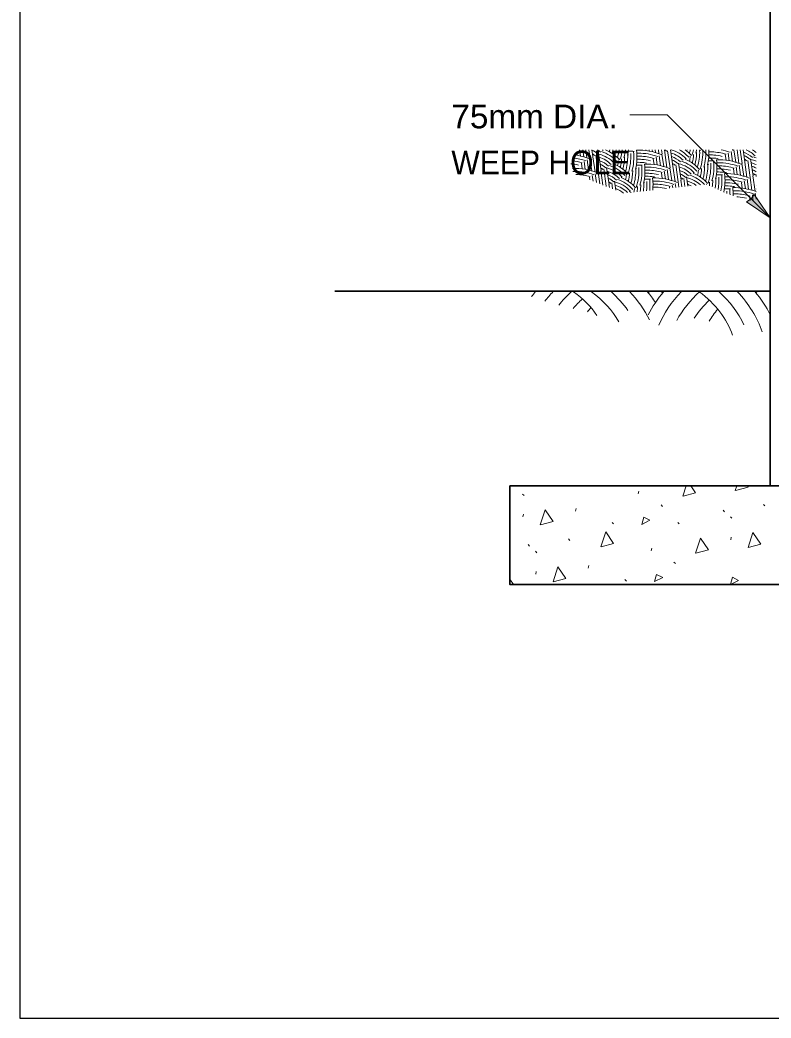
# Model space of a CAD drawing. Extents: x 17672 to 18472, y -9785 to -9267.
# Drawn here: x 17671.8 to 17783.6, y -9784.8 to -9636.2 of the extents above; entities that cross this region are included whole.
import ezdxf

# ---------------------------------------------------------------- set-up
doc = ezdxf.new("R2010")
doc.units = 0
doc.header["$LTSCALE"] = 1.4
for name, color, linetype, lineweight in [('1', 7, 'Continuous', 13), ('15', 7, 'Continuous', 13), ('16', 7, 'Continuous', 13), ('30', 7, 'Continuous', 25), ('59', 7, 'Continuous', 13)]:
    doc.layers.add(name, color=color, linetype=linetype, lineweight=lineweight)
doc.layers.add('19', color=7, linetype='Continuous')

msp = doc.modelspace()

# ---------------------------------------------------------------- hatches: boundary and pattern name
at = {"layer": '16'}
msp.add_hatch(color=256, dxfattribs=at).paths.add_polyline_path([(17783.439, -9665.599), (17781.072, -9662.116), (17780.648, -9662.802), (17779.937, -9663.248)])

# ---------------------------------------------------------------- linework, layer by layer
at = {"layer": '1', "lineweight": 35}
msp.add_line((17783.439, -9676.547), (17718.64, -9676.547), dxfattribs=at)
at = {"layer": '1', "lineweight": 25}
msp.add_line((17783.488, -9680.039), (17783.463, -9679.799), dxfattribs=at)
at = {"layer": '1'}
for p, q in [((17763.824, -9706.683), (17763.927, -9706.285)), ((17770.451, -9707.06), (17770.947, -9705.526)), ((17778.265, -9706.202), (17778.483, -9705.526)), ((17746.608, -9706.736), (17746.821, -9706.952)), ((17754.471, -9709.278), (17754.562, -9708.898)), ((17767.243, -9708.366), (17767.439, -9708.585)), ((17776.464, -9709.138), (17776.677, -9709.369)), ((17782.469, -9708.3), (17782.68, -9708.516)), ((17746.657, -9710.136), (17746.745, -9709.741)), ((17777.54, -9710.131), (17777.751, -9710.347)), ((17759.942, -9710.962), (17760.152, -9711.178)), ((17769.721, -9710.974), (17769.932, -9711.19)), ((17753.434, -9713.42), (17753.645, -9713.636)), ((17777.586, -9713.531), (17777.675, -9713.136)), ((17747.429, -9714.259), (17747.645, -9714.489)), ((17748.505, -9715.251), (17748.716, -9715.467)), ((17765.733, -9715.195), (17765.822, -9714.8)), ((17748.552, -9718.651), (17748.64, -9718.256)), ((17756.38, -9717.79), (17756.469, -9717.396)), ((17769.14, -9716.881), (17769.349, -9717.08)), ((17761.836, -9719.477), (17762.047, -9719.692))]:
    msp.add_line(p, q, dxfattribs=at)
at = {"layer": '1', "lineweight": 35}
for points in [[(17783.439, -9705.506), (17783.439, -9573.439), (17794.636, -9573.056), (17807.886, -9705.526), (17783.439, -9705.526)], [(17783.439, -9705.526), (17744.709, -9705.526), (17744.709, -9720.224), (17850.016, -9720.224), (17850.016, -9705.526), (17807.886, -9705.526)]]:
    msp.add_lwpolyline(points, close=True, dxfattribs=at)
at = {"layer": '1'}
for points in [[(17771.655, -9705.526), (17772.349, -9706.553), (17770.498, -9707.05)], [(17780.057, -9705.526), (17780.182, -9705.707), (17778.312, -9706.195)], [(17749.231, -9711.322), (17749.956, -9709.08), (17751.147, -9710.827), (17749.277, -9711.312)], [(17758.25, -9714.621), (17758.976, -9712.379), (17760.15, -9714.112), (17758.297, -9714.614)], [(17772.344, -9715.558), (17773.069, -9713.317), (17774.26, -9715.063), (17772.39, -9715.55)], [(17780.177, -9714.714), (17780.9, -9712.472), (17782.074, -9714.207), (17780.206, -9714.71)], [(17751.143, -9719.832), (17751.866, -9717.592), (17753.04, -9719.325), (17751.172, -9719.827)], [(17744.709, -9719.425), (17745.226, -9720.183), (17745.066, -9720.224)], [(17777.537, -9720.224), (17777.831, -9719.134), (17778.748, -9719.587), (17777.542, -9720.224)]]:
    msp.add_lwpolyline(points, dxfattribs=at)
for points in [[(17764.348, -9711.273), (17764.645, -9710.18), (17765.564, -9710.651)], [(17766.241, -9719.773), (17766.557, -9718.692), (17767.456, -9719.148)]]:
    msp.add_lwpolyline(points, close=True, dxfattribs=at)
for centre, major_axis, start_param, end_param in [((17771.279, -9686.608), (-26.675, 0), 5.7344252, 5.7796809), ((17771.279, -9686.608), (-24.471, 0), 5.6783592, 5.7742332), ((17771.279, -9686.608), (-22.266, 0), 5.6081662, 5.761688), ((17739.738, -9686.608), (20.062, 0), 0.4649367, 0.7655158), ((17742.389, -9686.608), (20.062, 0), 0.3930143, 0.7655158), ((17742.389, -9686.608), (22.266, 0), 0.4669224, 0.6750191), ((17742.389, -9686.608), (24.471, 0), 0.3369039, 0.6048262), ((17742.389, -9686.608), (26.675, 0), 0.4531045, 0.5487601), ((17790.366, -9686.608), (-26.675, 0), 5.7344252, 5.9359014), ((17744.407, -9662.857), (28.469, 0), 5.5360053, 5.5474825), ((17790.366, -9686.608), (-24.471, 0), 5.6783592, 5.9947455), ((17788.347, -9662.857), (-28.469, 0), 0.7357028, 0.74718), ((17790.366, -9686.608), (-22.266, 0), 5.6081662, 5.9189575), ((17758.423, -9686.608), (20.062, 0), 0.2476684, 0.7655158), ((17758.423, -9686.608), (22.266, 0), 0.321019, 0.6750191), ((17758.423, -9686.608), (24.471, 0), 0.230357, 0.6048262), ((17758.423, -9686.608), (26.675, 0), 0.3466408, 0.5487601), ((17760.442, -9662.857), (28.469, 0), 5.5360053, 5.5474825), ((17771.279, -9686.608), (-20.062, 0), 5.6168531, 5.7376933), ((17790.366, -9686.608), (-20.062, 0), 5.6332046, 5.8501484), ((17773.744, -9686.678), (-20.062, 0), 5.7208514, 5.7710521), ((17792.831, -9686.678), (-20.062, 0), 5.7400219, 5.8777396)]:
    msp.add_ellipse(centre, major_axis=major_axis, ratio=0.719298, start_param=start_param, end_param=end_param, dxfattribs=at)
at = {"layer": '15'}
msp.add_lwpolyline([(17762.574, -9650.256), (17768.128, -9650.256), (17783.439, -9665.599)], dxfattribs=at)
at = {"layer": '16'}
msp.add_lwpolyline([(17783.439, -9665.599), (17781.072, -9662.116), (17780.648, -9662.802), (17779.937, -9663.248)], close=True, dxfattribs=at)
at = {"layer": '30'}
for p, q in [((17671.774, -9267.105), (17671.774, -9784.752)), ((17671.774, -9784.752), (18471.773, -9784.752))]:
    msp.add_line(p, q, dxfattribs=at)
at = {"layer": '59'}
for p, q in [((17754.739, -9656.313), (17754.657, -9655.744)), ((17755.215, -9656.412), (17755.083, -9655.491)), ((17755.696, -9656.54), (17755.545, -9655.491)), ((17756.18, -9656.697), (17756.006, -9655.491)), ((17756.649, -9656.744), (17756.468, -9655.491)), ((17757.075, -9656.498), (17756.93, -9655.491)), ((17764.981, -9655.597), (17764.966, -9655.491)), ((17765.453, -9655.67), (17765.427, -9655.491)), ((17765.929, -9655.769), (17765.889, -9655.491)), ((17766.41, -9655.897), (17766.351, -9655.491)), ((17766.894, -9656.054), (17766.813, -9655.491)), ((17767.363, -9656.101), (17767.275, -9655.491)), ((17767.789, -9655.855), (17767.737, -9655.491)), ((17768.563, -9658.179), (17768.194, -9655.621)), ((17768.989, -9657.933), (17768.637, -9655.491)), ((17777.843, -9657.205), (17777.629, -9655.716)), ((17778.324, -9657.332), (17778.058, -9655.491)), ((17778.808, -9657.49), (17778.52, -9655.491)), ((17779.277, -9657.536), (17778.982, -9655.491)), ((17779.703, -9657.29), (17779.444, -9655.491)), ((17755.939, -9658.392), (17755.775, -9657.249)), ((17756.416, -9658.491), (17756.201, -9657.002)), ((17756.896, -9658.618), (17756.627, -9656.756)), ((17757.38, -9658.776), (17757.054, -9656.51)), ((17757.849, -9658.822), (17757.48, -9656.264)), ((17758.275, -9658.576), (17757.907, -9656.018)), ((17766.181, -9657.675), (17766.062, -9656.852)), ((17766.653, -9657.748), (17766.489, -9656.606)), ((17767.129, -9657.848), (17766.915, -9656.359)), ((17767.61, -9657.975), (17767.341, -9656.113)), ((17768.094, -9658.133), (17767.768, -9655.867)), ((17776.895, -9657.032), (17776.776, -9656.209)), ((17777.367, -9657.105), (17777.203, -9655.963)), ((17780.008, -9659.568), (17779.682, -9657.303)), ((17780.477, -9659.615), (17780.108, -9657.056)), ((17780.903, -9659.369), (17780.535, -9656.81)), ((17755.467, -9658.318), (17755.348, -9657.495)), ((17758.075, -9660.551), (17757.827, -9658.835)), ((17758.564, -9660.743), (17758.254, -9658.589)), ((17759.049, -9660.901), (17758.68, -9658.342)), ((17759.475, -9660.655), (17759.107, -9658.096)), ((17767.853, -9659.827), (17767.689, -9658.684)), ((17768.329, -9659.926), (17768.115, -9658.438)), ((17768.81, -9660.054), (17768.541, -9658.192)), ((17769.294, -9660.211), (17768.968, -9657.946)), ((17769.763, -9660.258), (17769.394, -9657.699)), ((17770.189, -9660.012), (17769.821, -9657.453)), ((17778.095, -9659.111), (17777.976, -9658.287)), ((17778.567, -9659.184), (17778.403, -9658.041)), ((17779.043, -9659.283), (17778.829, -9657.795)), ((17779.524, -9659.411), (17779.255, -9657.549)), ((17756.606, -9659.976), (17756.548, -9659.573)), ((17757.096, -9660.168), (17756.975, -9659.327)), ((17757.585, -9660.36), (17757.401, -9659.081)), ((17760.498, -9661.501), (17760.307, -9660.175)), ((17767.381, -9659.754), (17767.262, -9658.93)), ((17769.856, -9661.068), (17769.741, -9660.27)), ((17770.311, -9661.019), (17770.168, -9660.024)), ((17770.766, -9660.969), (17770.594, -9659.778)), ((17771.221, -9660.92), (17771.021, -9659.532)), ((17779.767, -9661.262), (17779.603, -9660.12)), ((17780.243, -9661.362), (17780.029, -9659.873)), ((17780.724, -9661.489), (17780.455, -9659.627)), ((17781.208, -9661.647), (17780.882, -9659.381)), ((17781.353, -9659.446), (17781.308, -9659.135)), ((17759.029, -9660.925), (17759.027, -9660.913)), ((17759.519, -9661.117), (17759.454, -9660.667)), ((17760.008, -9661.309), (17759.88, -9660.421)), ((17768.492, -9661.216), (17768.462, -9661.009)), ((17768.947, -9661.166), (17768.889, -9660.763)), ((17769.402, -9661.117), (17769.315, -9660.516)), ((17779.295, -9661.189), (17779.176, -9660.366)), ((17781.367, -9660.845), (17781.37, -9660.839)), ((17781.367, -9661.188), (17781.368, -9661.194)), ((17781.367, -9661.351), (17781.37, -9661.345)), ((17781.367, -9661.694), (17781.368, -9661.7)), ((17780.46, -9663.027), (17780.376, -9662.444)), ((17780.941, -9663.157), (17780.803, -9662.198)), ((17781.353, -9662.812), (17781.229, -9661.952)), ((17781.367, -9661.857), (17781.37, -9661.851))]:
    msp.add_line(p, q, dxfattribs=at)
for centre, radius, start, end in [((17755.635, -9658.526), 3.246, 48.61216, 66.31556), ((17755.635, -9658.526), 3.703, 46.24605, 55.02562), ((17756.835, -9660.604), 5.075, 41.78023, 72.61644), ((17755.635, -9658.526), 4.16, 44.41972, 46.83392), ((17756.835, -9660.604), 5.532, 40.79451, 67.56052), ((17753.774, -9654.464), 5.904, 347.18974, 349.98573), ((17753.774, -9654.464), 6.361, 345.79013, 350.71202), ((17753.774, -9654.464), 6.818, 344.20891, 351.33971), ((17753.774, -9654.464), 7.276, 342.46039, 351.88766), ((17753.774, -9654.464), 7.733, 341.27117, 352.37019), ((17753.774, -9654.464), 8.19, 344.79413, 352.79841), ((17753.774, -9654.464), 8.647, 347.76867, 353.181), ((17762.605, -9662.668), 6.976, 84.91667, 92.2433), ((17754.974, -9656.543), 8.19, 344.79413, 5.38027), ((17754.974, -9656.543), 8.647, 347.76867, 6.76088), ((17763.805, -9664.746), 9.225, 68.22949, 91.52069), ((17766.349, -9657.883), 2.789, 51.80648, 59.03375), ((17767.549, -9659.961), 4.618, 42.96583, 75.47493), ((17767.549, -9659.961), 5.075, 41.78023, 61.74331), ((17767.549, -9659.961), 5.532, 40.79451, 53.9054), ((17764.488, -9653.821), 6.818, 344.20891, 345.82509), ((17764.488, -9653.821), 7.276, 342.46039, 346.7326), ((17764.488, -9653.821), 7.733, 341.27117, 347.53), ((17764.488, -9653.821), 8.19, 344.79413, 348.23632), ((17765.688, -9655.9), 7.276, 342.46039, 2.03411), ((17764.488, -9653.821), 8.647, 347.76867, 348.86642), ((17773.319, -9662.025), 6.459, 92.10533, 93.23642), ((17765.688, -9655.9), 7.733, 341.27117, 3.03057), ((17765.688, -9655.9), 8.19, 344.79413, 2.86126), ((17765.688, -9655.9), 8.647, 347.76867, 2.70987), ((17774.519, -9664.103), 8.31, 88.04174, 91.27777), ((17774.519, -9664.103), 8.31, 73.38463, 88.04174), ((17774.519, -9664.103), 8.767, 70.62286, 79.19973), ((17774.519, -9664.103), 9.225, 68.22949, 69.00456), ((17778.263, -9659.318), 3.703, 46.24605, 70.61857), ((17778.263, -9659.318), 4.16, 44.41972, 66.90416), ((17778.263, -9659.318), 4.618, 47.99625, 55.97414), ((17753.091, -9665.389), 8.31, 73.38463, 83.7322), ((17753.091, -9665.389), 8.767, 70.62286, 82.69609), ((17753.091, -9665.389), 9.225, 68.22949, 81.76794), ((17755.635, -9658.526), 2.789, 51.80648, 60.2641), ((17756.835, -9660.604), 4.618, 42.96583, 76.40181), ((17756.835, -9660.604), 4.16, 44.41972, 73.86082), ((17756.835, -9660.604), 3.703, 46.24605, 70.61857), ((17754.974, -9656.543), 5.904, 347.18974, 354.69874), ((17754.974, -9656.543), 6.361, 345.79013, 357.5647), ((17754.974, -9656.543), 6.818, 344.20891, 359.9744), ((17754.974, -9656.543), 7.276, 342.46039, 2.03411), ((17762.605, -9662.668), 6.459, 92.10533, 93.23642), ((17754.974, -9656.543), 7.733, 341.27117, 3.8181), ((17763.805, -9664.746), 7.396, 83.50636, 91.726), ((17763.805, -9664.746), 8.767, 89.88729, 91.32638), ((17763.805, -9664.746), 7.853, 85.93639, 91.39999), ((17763.805, -9664.746), 8.31, 88.04174, 91.27777), ((17763.805, -9664.746), 8.767, 70.62286, 89.88729), ((17763.805, -9664.746), 8.31, 73.38463, 88.04174), ((17763.805, -9664.746), 7.853, 76.6253, 85.93639), ((17767.549, -9659.961), 4.16, 44.41972, 73.86082), ((17767.549, -9659.961), 3.703, 46.24605, 70.61857), ((17767.549, -9659.961), 3.246, 48.61216, 66.31556), ((17768.749, -9662.04), 5.075, 41.78023, 72.61644), ((17768.749, -9662.04), 5.532, 40.79451, 68.39902), ((17765.688, -9655.9), 5.904, 347.18974, 354.69874), ((17765.688, -9655.9), 6.361, 345.79013, 357.5647), ((17765.688, -9655.9), 6.818, 344.20891, 359.9744), ((17774.519, -9664.103), 6.976, 84.91667, 92.2433), ((17774.519, -9664.103), 7.396, 83.50636, 91.726), ((17774.519, -9664.103), 7.853, 85.93639, 91.39999), ((17766.888, -9657.978), 8.19, 344.79413, 5.38027), ((17774.519, -9664.103), 7.853, 76.6253, 85.93639), ((17766.888, -9657.978), 8.647, 347.76867, 6.76088), ((17774.519, -9664.103), 7.396, 80.51637, 83.50636), ((17775.719, -9666.182), 9.225, 68.22949, 91.52069), ((17778.263, -9659.318), 3.246, 48.61216, 66.31556), ((17778.263, -9659.318), 2.789, 51.80648, 60.2641), ((17779.463, -9661.397), 4.618, 65.83916, 76.40181), ((17779.463, -9661.397), 5.075, 68.1345, 72.61644), ((17753.091, -9665.389), 7.853, 76.6253, 84.8967), ((17754.291, -9667.468), 9.225, 68.22949, 91.52069), ((17754.291, -9667.468), 8.767, 89.88729, 91.32638), ((17754.291, -9667.468), 8.767, 70.62286, 89.88729), ((17756.835, -9660.604), 3.246, 48.61216, 66.31556), ((17756.835, -9660.604), 2.789, 51.80648, 60.2641), ((17758.035, -9662.683), 4.618, 42.96583, 76.40181), ((17758.035, -9662.683), 4.16, 44.41972, 73.86082), ((17758.035, -9662.683), 5.075, 41.78023, 72.61644), ((17758.035, -9662.683), 5.532, 40.79451, 68.39902), ((17756.174, -9658.621), 6.818, 344.20891, 359.9744), ((17756.174, -9658.621), 7.276, 342.46039, 2.03411), ((17763.805, -9664.746), 6.459, 92.10533, 93.23642), ((17756.174, -9658.621), 7.733, 341.27117, 3.8181), ((17763.805, -9664.746), 6.976, 84.91667, 92.2433), ((17756.174, -9658.621), 8.19, 344.79413, 5.38027), ((17756.174, -9658.621), 8.647, 347.76867, 6.76088), ((17763.805, -9664.746), 7.396, 80.51637, 83.50636), ((17765.005, -9666.825), 9.225, 68.22949, 91.52069), ((17765.005, -9666.825), 8.767, 89.88729, 91.32638), ((17765.005, -9666.825), 8.31, 88.04174, 91.27777), ((17765.005, -9666.825), 8.767, 70.62286, 89.88729), ((17765.005, -9666.825), 8.31, 73.38463, 88.04174), ((17767.549, -9659.961), 2.789, 51.80648, 60.2641), ((17768.749, -9662.04), 4.618, 42.96583, 76.40181), ((17768.749, -9662.04), 4.16, 44.41972, 73.86082), ((17768.749, -9662.04), 3.703, 46.24605, 70.61857), ((17766.888, -9657.978), 5.904, 347.18974, 354.69874), ((17766.888, -9657.978), 6.361, 345.79013, 357.5647), ((17766.888, -9657.978), 6.818, 344.20891, 359.9744), ((17766.888, -9657.978), 7.276, 342.46039, 2.03411), ((17774.519, -9664.103), 6.459, 92.10533, 93.23642), ((17766.888, -9657.978), 7.733, 341.27117, 3.8181), ((17775.719, -9666.182), 7.396, 83.50636, 91.726), ((17775.719, -9666.182), 8.767, 89.88729, 91.32638), ((17775.719, -9666.182), 7.853, 85.93639, 91.39999), ((17775.719, -9666.182), 8.31, 88.04174, 91.27777), ((17775.719, -9666.182), 8.767, 70.62286, 89.88729), ((17775.719, -9666.182), 8.31, 73.38463, 88.04174), ((17775.719, -9666.182), 7.853, 76.6253, 85.93639), ((17775.719, -9666.182), 7.396, 80.51637, 83.50636), ((17779.463, -9661.397), 4.16, 62.98188, 73.86083), ((17779.463, -9661.397), 3.703, 59.31298, 70.61857), ((17779.463, -9661.397), 3.246, 54.39332, 66.31556), ((17754.291, -9667.468), 8.31, 88.04174, 88.38657), ((17754.291, -9667.468), 8.31, 73.38463, 88.04174), ((17758.035, -9662.683), 3.703, 46.24605, 70.61857), ((17758.035, -9662.683), 3.246, 48.61216, 66.31556), ((17758.035, -9662.683), 2.789, 51.80648, 60.2641), ((17759.235, -9664.761), 4.618, 42.96583, 76.40181), ((17759.235, -9664.761), 5.075, 41.78023, 72.61644), ((17759.235, -9664.761), 5.532, 40.79451, 68.39902), ((17756.174, -9658.621), 5.904, 347.18974, 354.69874), ((17756.174, -9658.621), 6.361, 345.79013, 357.5647), ((17765.005, -9666.825), 6.976, 84.91667, 92.2433), ((17765.005, -9666.825), 7.396, 83.50636, 91.726), ((17765.005, -9666.825), 7.853, 85.93639, 91.39999), ((17757.374, -9660.7), 7.733, 353.40547, 3.8181), ((17757.374, -9660.7), 8.19, 354.12961, 5.38027), ((17765.005, -9666.825), 7.853, 76.6253, 85.93639), ((17765.005, -9666.825), 7.396, 80.51637, 83.50636), ((17766.205, -9668.903), 9.225, 68.22949, 91.52069), ((17757.374, -9660.7), 8.647, 354.77554, 6.76088), ((17766.205, -9668.903), 8.767, 89.88729, 91.32638), ((17766.205, -9668.903), 8.767, 70.62286, 89.88729), ((17768.749, -9662.04), 3.246, 48.61216, 66.31556), ((17768.749, -9662.04), 2.789, 51.80648, 60.2641), ((17769.949, -9664.118), 4.618, 47.39379, 76.40181), ((17769.949, -9664.118), 4.16, 53.17242, 73.86083), ((17769.949, -9664.118), 5.075, 43.01553, 72.61644), ((17769.949, -9664.118), 5.532, 40.79451, 68.39902), ((17768.088, -9660.057), 6.818, 351.88467, 359.9744), ((17768.088, -9660.057), 7.276, 350.89669, 2.03411), ((17775.719, -9666.182), 6.459, 92.10533, 93.23642), ((17775.719, -9666.182), 6.976, 84.91667, 92.2433), ((17768.088, -9660.057), 7.733, 350.02915, 3.8181), ((17768.088, -9660.057), 8.19, 349.26111, 5.38027), ((17768.088, -9660.057), 8.647, 348.57626, 6.76088), ((17776.919, -9668.26), 9.225, 68.22949, 91.52069), ((17776.919, -9668.26), 8.767, 89.88729, 91.32638), ((17776.919, -9668.26), 8.31, 88.04174, 91.27777), ((17776.919, -9668.26), 8.767, 70.62286, 89.88729), ((17776.919, -9668.26), 8.31, 73.38463, 88.04174), ((17779.463, -9661.397), 2.789, 51.80648, 60.2641), ((17759.235, -9664.761), 4.16, 44.41972, 73.86082), ((17759.235, -9664.761), 3.703, 49.35911, 70.61857), ((17760.435, -9666.84), 5.532, 64.82016, 68.39902), ((17757.374, -9660.7), 5.904, 349.34587, 354.69874), ((17757.374, -9660.7), 6.361, 350.58779, 357.5647), ((17757.374, -9660.7), 6.818, 351.65711, 359.9744), ((17757.374, -9660.7), 7.276, 352.58783, 2.03411), ((17765.005, -9666.825), 6.459, 92.10533, 93.23642), ((17766.205, -9668.903), 7.853, 85.93639, 91.39999), ((17766.205, -9668.903), 8.31, 88.04174, 91.27777), ((17766.205, -9668.903), 8.31, 73.38463, 88.04174), ((17766.205, -9668.903), 7.853, 76.6253, 85.93639), ((17769.949, -9664.118), 3.703, 61.41812, 70.61857), ((17768.088, -9660.057), 5.904, 354.34049, 354.69874), ((17768.088, -9660.057), 6.361, 353.02044, 357.5647), ((17776.919, -9668.26), 6.976, 84.91667, 92.2433), ((17776.919, -9668.26), 6.459, 92.10533, 92.39143), ((17776.919, -9668.26), 7.396, 83.50636, 91.726), ((17776.919, -9668.26), 7.853, 85.93639, 91.39999), ((17769.288, -9662.135), 7.733, 1.24477, 3.8181), ((17769.288, -9662.135), 8.19, 359.77953, 5.38027), ((17776.919, -9668.26), 7.853, 76.6253, 85.93639), ((17776.919, -9668.26), 7.396, 80.51637, 83.50636), ((17778.119, -9670.339), 9.225, 69.47907, 91.52069), ((17769.288, -9662.135), 8.647, 358.64231, 6.76088), ((17778.119, -9670.339), 8.767, 89.88729, 91.32638), ((17778.119, -9670.339), 8.767, 70.62286, 89.88729), ((17778.119, -9670.339), 8.31, 88.04174, 91.27777), ((17778.119, -9670.339), 8.31, 73.38463, 88.04174), ((17778.119, -9670.339), 7.853, 85.93639, 87.20878), ((17778.119, -9670.339), 7.853, 76.6253, 85.93639)]:
    msp.add_arc(centre, radius, start, end, dxfattribs=at)

# ---------------------------------------------------------------- texts
at = {"layer": '19'}
for s, width, p in [('75mm DIA.', 1.05, (17735.998, -9652.29)), ('WEEP HOLE', 0.95, (17735.998, -9659.14))]:
    msp.add_text(s, height=3.529, dxfattribs=dict(at, width=width)).set_placement(p)

doc.saveas('drawing.dxf')
